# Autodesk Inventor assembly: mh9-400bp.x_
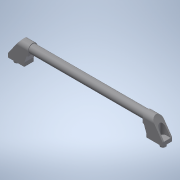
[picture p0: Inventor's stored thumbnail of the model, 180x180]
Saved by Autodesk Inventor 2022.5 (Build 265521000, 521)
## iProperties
Part Number: mh9-400bp.x_
Material: 一般
Document SubType Name: Assembly
Designer: ImaoCorp
Sending System: SOLIDWORKS 2017-2017317
MC: AMD64
MC_MODEL: Intel64 Family 6 Model 60 Stepping 3, GenuineIntel
OS: Windows_NT
FRU: Parasolid Version 29.0, build 201,  4-17-2017
FORMAT: text
GUISE: transmit
KEY: mh9-400bp
FILE: mh9-400bp.x_t
DATE: Fri Jul 26 11:47:35 2019
Author: ImaoCorp
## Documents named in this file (4)
- X:\14_SW2022-Inv2022\00_全2023-1023新製品(TCC)まで\m\mh9-400bp\MH9-400BP.iam
- X:\14_SW2022-Inv2022\00_全2023-1023新製品(TCC)まで\m\mh9-400bp\mh9-400bp_01.ipt
- X:\14_SW2022-Inv2022\00_全2023-1023新製品(TCC)まで\m\mh9-400bp\mh9-400bp_02.ipt
- X:\14_SW2022-Inv2022\00_全2023-1023新製品(TCC)まで\m\mh9-400bp\mh9-400bp_03.ipt
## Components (3 placed, 3 different names)
1. mh9-400bp_01
2. mh9-400bp_02
3. mh9-400bp_03
